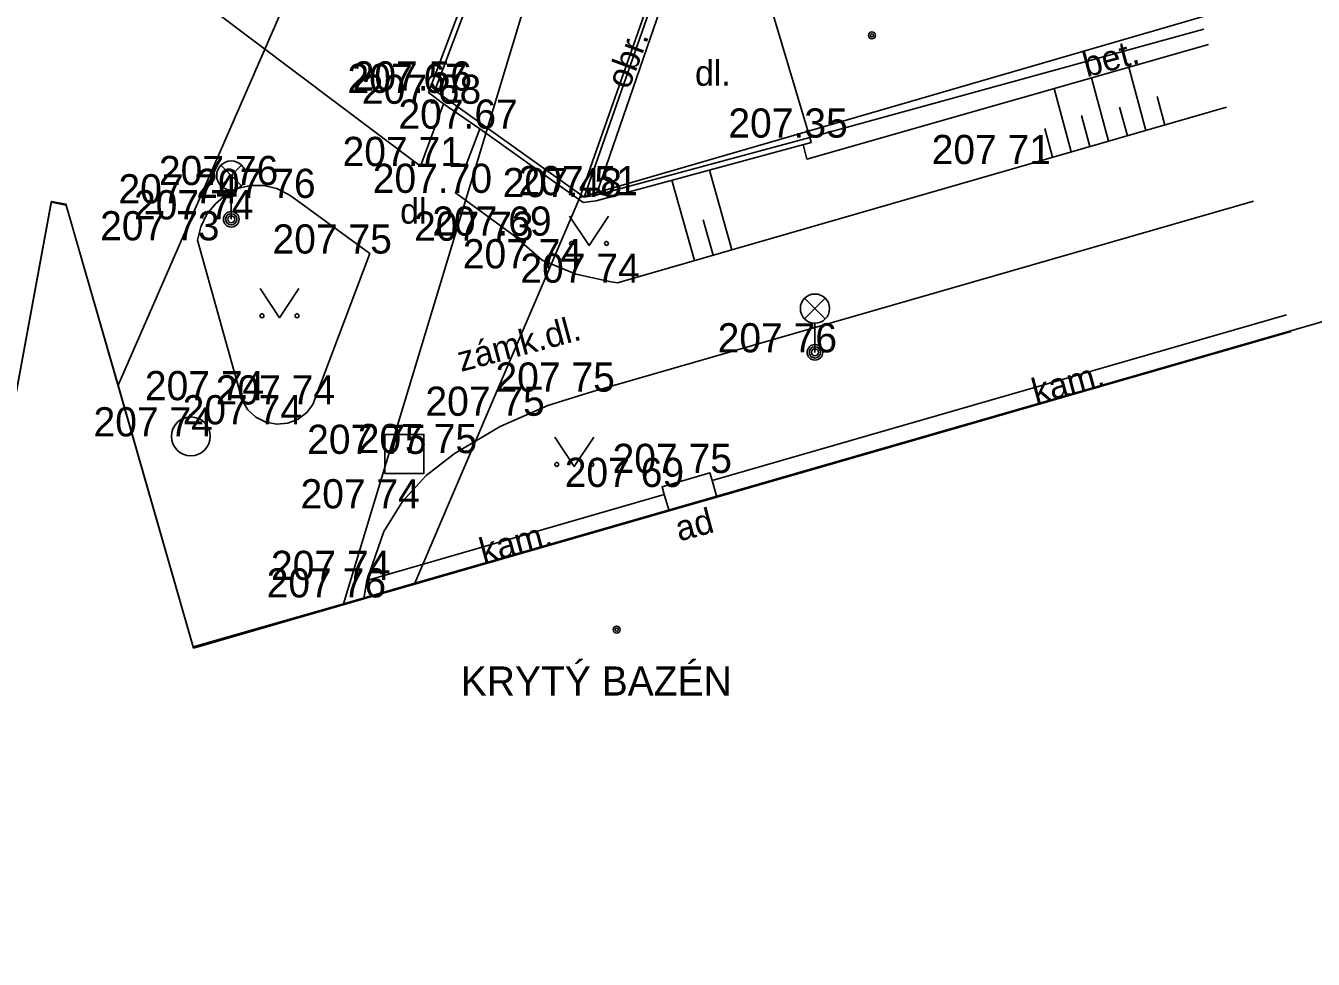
# Model space of a CAD drawing. Extents: x -524633 to -524336, y -1187893 to -1187683.
# Drawn here: x -524582.72 to -524549.63, y -1187865 to -1187841 of the extents above; entities that cross this region are included whole.
import ezdxf

# ---------------------------------------------------------------- set-up
doc = ezdxf.new("R2010")
doc.units = 0
for name, color, linetype in [('Hranice parcel', 7, 'Continuous'), ('Vrstva 1', 7, 'Continuous'), ('Vrstva 10', 7, 'Continuous'), ('Vrstva 11', 7, 'Continuous'), ('Vrstva 15', 7, 'Continuous'), ('Vrstva 26', 7, 'Continuous'), ('Vrstva 27', 7, 'Continuous'), ('Vrstva 3', 7, 'Continuous'), ('Vrstva 33', 7, 'Continuous'), ('Vrstva 36', 7, 'Continuous'), ('Vrstva 39', 7, 'Continuous'), ('Vrstva 4', 7, 'Continuous'), ('Vrstva 40', 7, 'Continuous'), ('Vrstva 41', 7, 'Continuous'), ('Vrstva 5', 7, 'Continuous')]:
    doc.layers.add(name, color=color, linetype=linetype)

msp = doc.modelspace()

# ---------------------------------------------------------------- linework, layer by layer
at = {"layer": 'Hranice parcel'}
for p, q in [((-524565.28, -1187836.31), (-524568.48, -1187845.42)), ((-524572.72, -1187855.33), (-524574.56, -1187855.86))]:
    msp.add_line(p, q, dxfattribs=at)
for points in [[(-524580.35, -1187850.24), (-524549.33, -1187779.18), (-524535.82, -1187753.93), (-524537.02, -1187750.93)], [(-524522.64, -1187765.24), (-524544.8, -1187788.23), (-524550.29, -1187795.7), (-524555.07, -1187804.42), (-524565.53, -1187826.01), (-524574.56, -1187855.86)], [(-524568.48, -1187845.42), (-524564.17, -1187844.17), (-524544.88, -1187838.56), (-524538.63, -1187836.75)], [(-524513.33, -1187865), (-524517.14, -1187851.8), (-524520.09, -1187852.66), (-524520.88, -1187849.93), (-524529.45, -1187852.43), (-524532.01, -1187843.6), (-524572.72, -1187855.33)], [(-524572.72, -1187855.33), (-524571.81, -1187853.18), (-524568.48, -1187845.42)], [(-524580.35, -1187850.24), (-524581.69, -1187845.59), (-524582.06, -1187845.52), (-524584.83, -1187860.5)], [(-524574.56, -1187855.86), (-524578.42, -1187856.97), (-524580.35, -1187850.24)]]:
    msp.add_lwpolyline(points, dxfattribs=at)
at = {"layer": 'Vrstva 1'}
for p, q in [((-524572.36, -1187842.73), (-524572.36, -1187842.73)), ((-524572.21, -1187842.67), (-524572.21, -1187842.67)), ((-524571.99, -1187843.01), (-524571.99, -1187843.01)), ((-524571.05, -1187843.65), (-524571.05, -1187843.65)), ((-524562.57, -1187843.88), (-524562.57, -1187843.88)), ((-524572.58, -1187844.61), (-524572.58, -1187844.61)), ((-524556.94, -1187844.56), (-524556.94, -1187844.56)), ((-524576.8, -1187845.1), (-524576.8, -1187845.1)), ((-524575.84, -1187845.43), (-524575.84, -1187845.43)), ((-524571.68, -1187845.3), (-524571.68, -1187845.3)), ((-524568.37, -1187845.41), (-524568.37, -1187845.41)), ((-524568.06, -1187845.36), (-524568.06, -1187845.36)), ((-524582.07, -1187845.54), (-524582.07, -1187845.54)), ((-524581.68, -1187845.62), (-524581.68, -1187845.62)), ((-524577.84, -1187845.57), (-524577.84, -1187845.57)), ((-524577.44, -1187845.98), (-524577.44, -1187845.98)), ((-524570.18, -1187846.4), (-524570.18, -1187846.4)), ((-524578.31, -1187846.52), (-524578.31, -1187846.52)), ((-524573.88, -1187846.86), (-524573.88, -1187846.86)), ((-524568.99, -1187847.24), (-524568.99, -1187847.24)), ((-524567.51, -1187847.61), (-524567.51, -1187847.61)), ((-524562.44, -1187849.4), (-524562.44, -1187849.4)), ((-524568.15, -1187850.41), (-524568.15, -1187850.41)), ((-524577.16, -1187850.63), (-524577.16, -1187850.63)), ((-524575.34, -1187850.74), (-524575.34, -1187850.74)), ((-524569.95, -1187851.03), (-524569.95, -1187851.03)), ((-524576.19, -1187851.25), (-524576.19, -1187851.25)), ((-524578.48, -1187851.56), (-524578.48, -1187851.56)), ((-524572.99, -1187852.01), (-524572.99, -1187852.01)), ((-524571.69, -1187851.99), (-524571.69, -1187851.99)), ((-524565.14, -1187852.5), (-524565.14, -1187852.5)), ((-524566.37, -1187852.86), (-524566.37, -1187852.86)), ((-524573.16, -1187853.41), (-524573.16, -1187853.41)), ((-524573.92, -1187855.25), (-524573.92, -1187855.25)), ((-524574.03, -1187855.7), (-524574.03, -1187855.7)), ((-524578.41, -1187857), (-524578.41, -1187857))]:
    msp.add_line(p, q, dxfattribs=at)
at = {"layer": 'Vrstva 10'}
msp.add_lwpolyline([(-524566.189, -1187853.477), (-524566.313, -1187853.053), (-524566.37, -1187852.86), (-524565.14, -1187852.5), (-524565.082, -1187852.697), (-524564.958, -1187853.122)], dxfattribs=at)
at = {"layer": 'Vrstva 11'}
for p, q in [((-524577.16, -1187850.63), (-524578.31, -1187846.52)), ((-524565.082, -1187852.697), (-524550.324, -1187848.434)), ((-524573.956, -1187855.26), (-524566.313, -1187853.053))]:
    msp.add_line(p, q, dxfattribs=at)
for points in [[(-524562.68, -1187811.77), (-524564.18, -1187818.1), (-524563.797, -1187818.32), (-524563.61, -1187818.556), (-524563.532, -1187818.95), (-524563.595, -1187819.264), (-524568.591, -1187832.674), (-524569.493, -1187835.073), (-524572.367, -1187842.718), (-524571.99, -1187843.01), (-524571.05, -1187843.65), (-524568.395, -1187845.551), (-524568.06, -1187845.502), (-524562.536, -1187844.006), (-524562.569, -1187843.88)], [(-524562.54, -1187811.73), (-524564.049, -1187818.02), (-524563.71, -1187818.22), (-524563.489, -1187818.5), (-524563.399, -1187818.95), (-524563.47, -1187819.3), (-524568.469, -1187832.72), (-524572.21, -1187842.67), (-524568.369, -1187845.41), (-524568.06, -1187845.36), (-524562.569, -1187843.88)], [(-524571.99, -1187843.01), (-524572.58, -1187844.61), (-524578.969, -1187839.8), (-524577.87, -1187833.69), (-524576.57, -1187833.66), (-524575.68, -1187833.49), (-524574.809, -1187833.25), (-524573.78, -1187832.87), (-524572.81, -1187832.35), (-524571.89, -1187831.74), (-524570.779, -1187830.73), (-524570.08, -1187829.86), (-524569.23, -1187828.47), (-524568.57, -1187827.08), (-524568.199, -1187825.78), (-524567.989, -1187824.27), (-524568.029, -1187822.95), (-524568.219, -1187821.6), (-524568.619, -1187820.21), (-524569.07, -1187819.11)], [(-524565.81, -1187838.81), (-524566.049, -1187838.77), (-524568.369, -1187845.41)], [(-524568.06, -1187845.36), (-524565.81, -1187838.81)], [(-524552.328, -1187841.484), (-524562.646, -1187844.431), (-524562.74, -1187844.06)], [(-524551.862, -1187843.099), (-524556.94, -1187844.56), (-524567.51, -1187847.61)], [(-524571.05, -1187843.65), (-524571.679, -1187845.3), (-524570.179, -1187846.4)], [(-524577.84, -1187845.57), (-524577.581, -1187845.348), (-524577.277, -1187845.192), (-524576.945, -1187845.111), (-524576.604, -1187845.109), (-524576.271, -1187845.186), (-524575.966, -1187845.338), (-524575.84, -1187845.43)], [(-524575.84, -1187845.43), (-524573.88, -1187846.86), (-524575.34, -1187850.74)], [(-524578.31, -1187846.52), (-524578.224, -1187846.169), (-524578.064, -1187845.846), (-524577.84, -1187845.57)], [(-524568.15, -1187850.41), (-524551.166, -1187845.514)], [(-524570.179, -1187846.4), (-524569.449, -1187847.029), (-524568.585, -1187847.386), (-524567.673, -1187847.59), (-524567.51, -1187847.61)], [(-524571.69, -1187851.99), (-524570.532, -1187851.308), (-524569.302, -1187850.767), (-524568.15, -1187850.41)], [(-524577.16, -1187850.63), (-524577.013, -1187850.874), (-524576.805, -1187851.068), (-524576.551, -1187851.196), (-524576.271, -1187851.249), (-524575.987, -1187851.223), (-524575.722, -1187851.119), (-524575.496, -1187850.946), (-524575.34, -1187850.74)], [(-524574.035, -1187855.739), (-524573.956, -1187855.26), (-524573.515, -1187854.008), (-524573.036, -1187853.237), (-524572.429, -1187852.563), (-524571.714, -1187852.005), (-524571.69, -1187851.99)]]:
    msp.add_lwpolyline(points, dxfattribs=at)
at = {"layer": 'Vrstva 15'}
for p, q in [((-524553.932, -1187843.695), (-524554.372, -1187842.068)), ((-524554.892, -1187843.971), (-524555.333, -1187842.342)), ((-524555.853, -1187844.247), (-524556.294, -1187842.617)), ((-524553.451, -1187843.556), (-524553.649, -1187842.823)), ((-524554.411, -1187843.833), (-524554.611, -1187843.095)), ((-524555.373, -1187844.109), (-524555.589, -1187843.311)), ((-524556.334, -1187844.386), (-524556.534, -1187843.648)), ((-524565.148, -1187844.713), (-524564.577, -1187846.764)), ((-524566.114, -1187844.975), (-524565.538, -1187847.041)), ((-524565.31, -1187845.995), (-524565.057, -1187846.902))]:
    msp.add_line(p, q, dxfattribs=at)
at = {"layer": 'Vrstva 26'}
msp.add_lwpolyline([(-524573.49, -1187852.51), (-524572.49, -1187852.51), (-524572.49, -1187851.51), (-524573.49, -1187851.51)], close=True, dxfattribs=at)
at = {"layer": 'Vrstva 27'}
msp.add_circle((-524578.48, -1187851.56), 0.5, dxfattribs=at)
at = {"layer": 'Vrstva 33'}
for p, q in [((-524577.705, -1187845.12), (-524577.175, -1187844.59)), ((-524577.705, -1187844.59), (-524577.175, -1187845.12)), ((-524577.44, -1187845.23), (-524577.44, -1187845.98)), ((-524562.705, -1187848.54), (-524562.175, -1187848.01)), ((-524562.705, -1187848.01), (-524562.175, -1187848.54)), ((-524562.44, -1187848.65), (-524562.44, -1187849.4))]:
    msp.add_line(p, q, dxfattribs=at)
for centre, radius in [((-524577.44, -1187844.855), 0.375), ((-524577.44, -1187845.98), 0.2), ((-524577.44, -1187845.98), 0.145), ((-524577.44, -1187845.98), 0.0876), ((-524562.44, -1187848.275), 0.375), ((-524562.44, -1187849.4), 0.2), ((-524562.44, -1187849.4), 0.145), ((-524562.44, -1187849.4), 0.0876)]:
    msp.add_circle(centre, radius, dxfattribs=at)
at = {"layer": 'Vrstva 36'}
for points in [[(-524568.745, -1187845.9), (-524568.245, -1187846.65), (-524567.745, -1187845.9)], [(-524576.7, -1187847.758), (-524576.2, -1187848.508), (-524575.7, -1187847.758)], [(-524569.125, -1187851.581), (-524568.625, -1187852.331), (-524568.125, -1187851.581)]]:
    msp.add_lwpolyline(points, dxfattribs=at)
for centre in [(-524568.695, -1187846.6), (-524567.796, -1187846.6), (-524576.65, -1187848.458), (-524575.751, -1187848.458), (-524569.075, -1187852.281), (-524568.176, -1187852.281)]:
    msp.add_circle(centre, 0.05, dxfattribs=at)
at = {"layer": 'Vrstva 39'}
for centre, radius in [((-524560.975, -1187841.252), 0.09), ((-524560.975, -1187841.252), 0.0398), ((-524567.533, -1187856.526), 0.09), ((-524567.533, -1187856.526), 0.0398)]:
    msp.add_circle(centre, radius, dxfattribs=at)
at = {"layer": 'Vrstva 5'}
for p, q in [((-524562.569, -1187843.88), (-524563.789, -1187839.79)), ((-524552.442, -1187841.088), (-524562.569, -1187843.88)), ((-524582.07, -1187845.54), (-524585.2, -1187862.499)), ((-524581.68, -1187845.62), (-524582.07, -1187845.54)), ((-524578.41, -1187857), (-524581.68, -1187845.62))]:
    msp.add_line(p, q, dxfattribs=at)
msp.add_lwpolyline([(-524550.2, -1187848.867), (-524564.958, -1187853.122), (-524566.189, -1187853.477), (-524574.035, -1187855.739), (-524578.41, -1187857)], dxfattribs=at)

# ---------------------------------------------------------------- texts
at = {"layer": 'Vrstva 3'}
for s, p in [('207.67', (-524574.454, -1187842.73)), ('207.35', (-524564.665, -1187843.88)), ('207 71 ', (-524559.44, -1187844.56)), ('207.70', (-524573.804, -1187845.3)), ('207 74 ', (-524571.49, -1187847.24)), ('207 76 ', (-524564.94, -1187849.4)), ('207 75 ', (-524570.65, -1187850.41)), ('207 75 ', (-524567.64, -1187852.5))]:
    msp.add_text(s, height=0.75, dxfattribs=at).set_placement(p)
at = {"layer": 'Vrstva 4'}
for s, p in [('207.56', (-524574.321, -1187842.67)), ('207.68', (-524574.084, -1187843.01)), ('207.67', (-524573.144, -1187843.65)), ('207.71', (-524574.58, -1187844.61)), ('207 76 ', (-524579.3, -1187845.1)), ('207 74 ', (-524580.34, -1187845.57)), ('207 76 ', (-524578.34, -1187845.43)), ('207.48', (-524570.464, -1187845.41)), ('207.51', (-524570.06, -1187845.36)), ('207 74 ', (-524579.94, -1187845.98)), ('207 73 ', (-524580.81, -1187846.52)), ('207 73 ', (-524572.74, -1187846.53)), ('207.69', (-524572.274, -1187846.4)), ('207 75 ', (-524576.38, -1187846.86)), ('207 74 ', (-524570.01, -1187847.61)), ('207 74 ', (-524579.66, -1187850.63)), ('207 74 ', (-524577.84, -1187850.74)), ('207 75 ', (-524572.45, -1187851.03)), ('207 74 ', (-524578.69, -1187851.25)), ('207 74 ', (-524580.98, -1187851.56)), ('207 75 ', (-524575.49, -1187852.01)), ('207 75 ', (-524574.19, -1187851.99)), ('207 69 ', (-524568.87, -1187852.86)), ('207 74 ', (-524575.66, -1187853.41)), ('207 74 ', (-524576.42, -1187855.25)), ('207 76 ', (-524576.53, -1187855.7))]:
    msp.add_text(s, height=0.75, dxfattribs=at).set_placement(p)
at = {"layer": 'Vrstva 40'}
for s, rotation, p in [('obr.', 69.3974, (-524567.223, -1187842.668)), ('bet.', 15, (-524555.456, -1187842.331)), ('zámk.dl.', 15, (-524571.534, -1187849.905)), ('kam.', 15, (-524556.764, -1187850.733)), ('ad', 15, (-524565.927, -1187854.263)), ('kam.', 15, (-524570.96, -1187854.835))]:
    msp.add_text(s, height=0.65, rotation=rotation, dxfattribs=at).set_placement(p)
for p in [(-524565.522, -1187842.546), (-524573.1, -1187846.091)]:
    msp.add_text('dl.', height=0.65, dxfattribs=at).set_placement(p)
at = {"layer": 'Vrstva 41'}
msp.add_text('KRYTÝ BAZÉN', height=0.75, dxfattribs=at).set_placement((-524571.543, -1187858.223))

doc.saveas('drawing.dxf')
